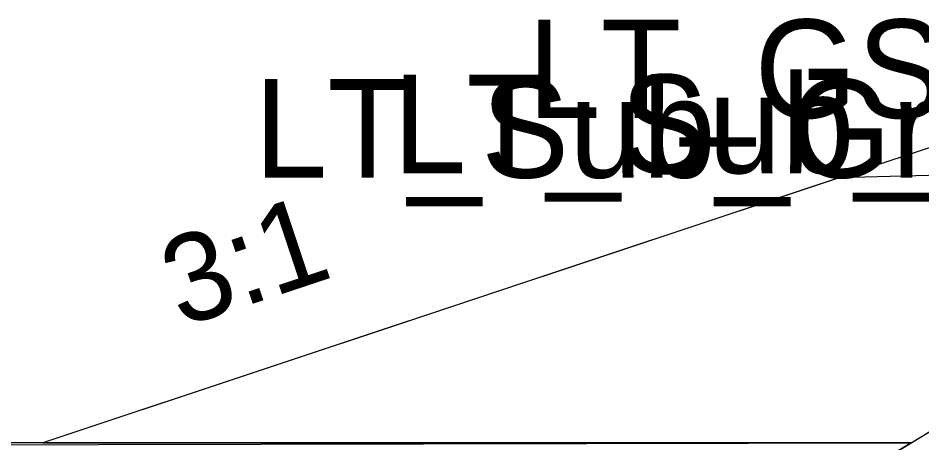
# Model space of a CAD drawing. Extents: x -14026 to 1303, y -10 to 9533.
# Drawn here: x 118.59 to 128.9, y 5003.88 to 5008.73 of the extents above; entities that cross this region are included whole.
import ezdxf

# ---------------------------------------------------------------- set-up
doc = ezdxf.new("R2010")
doc.units = 0
for name, color, linetype in [('Exist XS Ground Line', 7, 'Continuous'), ('Old_Level_10', 7, 'Continuous'), ('Prop CMT Slope Grass', 7, 'Continuous'), ('Prop CMT Subgrade Earthwork', 7, 'Continuous'), ('Prop XS Earthwork Shape', 7, 'Continuous'), ('Prop XS Side Slope Text', 7, 'Continuous'), ('Scratch_Level_0', 7, 'Continuous'), ('Scratch_Level_3', 7, 'Continuous')]:
    doc.layers.add(name, color=color, linetype=linetype)

msp = doc.modelspace()

# ---------------------------------------------------------------- linework, layer by layer
at = {"layer": 'Exist XS Ground Line'}
msp.add_lwpolyline([(74.654, 5002.365), (84.122, 5002.607), (86.233, 5002.67), (87.741, 5002.66), (94.101, 5002.493), (95.538, 5002.49), (121.648, 5001.571), (124.073, 5001.478), (124.8, 5001.452), (125.798, 5002.067), (129.983, 5004.611)], dxfattribs=at)
at = {"layer": 'Old_Level_10'}
msp.add_lwpolyline([(112.793, 5001.854), (115.793, 5003.854), (128.78, 5003.88), (124.8, 5001.452)], close=True, dxfattribs=at)
at = {"layer": 'Prop CMT Slope Grass'}
msp.add_line((118.871, 5003.88), (128.78, 5003.88), dxfattribs=at)
msp.add_lwpolyline([(130, 5007.586), (118.871, 5003.88)], dxfattribs=at)
at = {"layer": 'Prop CMT Subgrade Earthwork'}
msp.add_line((118.871, 5003.88), (128.78, 5003.88), dxfattribs=at)
for points in [[(130, 5006.957), (127.96, 5006.906)], [(127.96, 5006.906), (118.871, 5003.88)]]:
    msp.add_lwpolyline(points, dxfattribs=at)
at = {"layer": 'Prop XS Earthwork Shape'}
for points in [[(138.553, 5007.145), (140.356, 5007.255), (142.565, 5007.47), (144.664, 5007.947), (144.98, 5008.005), (146.322, 5008.001), (150, 5007.97), (155.9, 5007.921), (160.748, 5008.085), (161.652, 5008.124), (150, 5008.416), (142.565, 5008.23), (138, 5008.116), (136, 5008.066), (130, 5007.586), (118.871, 5003.88), (128.78, 5003.88), (129.983, 5004.611), (131.738, 5005.082), (133.93, 5005.614), (134.761, 5005.87)], [(134.517, 5007.07), (130, 5006.957), (127.96, 5006.906), (118.871, 5003.88), (128.78, 5003.88), (129.983, 5004.611), (131.738, 5005.082), (133.93, 5005.614), (134.761, 5005.87), (138.553, 5007.145), (139.273, 5007.189), (138, 5007.157)]]:
    msp.add_lwpolyline(points, close=True, dxfattribs=at)
at = {"layer": 'Scratch_Level_3'}
msp.add_line((128.78, 5003.88), (105.602, 5003.88), dxfattribs=at)

# ---------------------------------------------------------------- texts
at = {"layer": 'Prop XS Side Slope Text'}
msp.add_text('3:1', height=1, rotation=18.4178, dxfattribs=at).set_placement((120.444, 5005.194))
at = {"layer": 'Scratch_Level_0'}
for s, p in [('LT_GS_OS_CTL', (124.4, 5007.586)), ('LT_Sub_Graded_Tie', (121.281, 5006.906)), ('LT_Sub_Graded_CTL', (122.866, 5006.957))]:
    msp.add_text(s, height=1.125, dxfattribs=at).set_placement(p)

doc.saveas('drawing.dxf')
